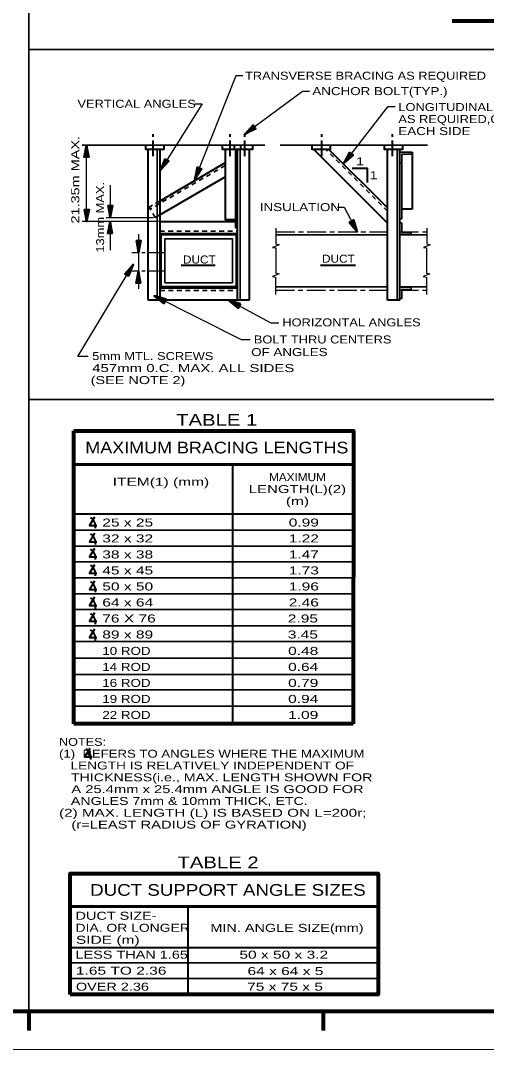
# Model space of a CAD drawing. Extents: x 55 to 190, y 198 to 264.
# Drawn here: x 102.33 to 117.13, y 198.45 to 231.1 of the extents above; entities that cross this region are included whole.
import ezdxf
from ezdxf.enums import TextEntityAlignment as Align

# ---------------------------------------------------------------- set-up
doc = ezdxf.new("R2010")
doc.units = 0
doc.header["$LTSCALE"] = 0.1
for name, pattern in [('DOT_DASHED', [7.7, 5, -1.2, 0.3, -1.2]), ('LONG_DASH_SHORT_DASH', [9.9, 6, -1.2, 1.5, -1.2]), ('SHORT_DASHED', [2.7, 1.5, -1.2])]:
    doc.linetypes.add(name, pattern=pattern)
doc.layers.add('1', color=7, linetype='Continuous', lineweight=25)
doc.layers.add('2', color=7, linetype='Continuous', lineweight=40)

msp = doc.modelspace()

# ---------------------------------------------------------------- linework, layer by layer
at = {"layer": '1', "lineweight": 80}
for p, q in [((102.5927, 199.6512), (102.5927, 199.0512)), ((111.9427, 199.6512), (111.9427, 199.0512))]:
    msp.add_line(p, q, dxfattribs=at)
at = {"layer": '1', "lineweight": 13}
msp.add_lwpolyline([(62.4915, 257.8525), (146.5927, 257.8525), (146.5927, 198.4512), (62.4915, 198.4512)], close=True, dxfattribs=at)
at = {"layer": '1', "lineweight": 80}
msp.add_lwpolyline([(65.1915, 256.6525), (145.3927, 256.6525), (145.3927, 199.6512), (65.1915, 199.6512)], close=True, dxfattribs=at)
at = {"layer": '2', "lineweight": 35}
for p, q in [((102.5927, 256.6525), (102.5927, 199.6512)), ((102.5927, 230.1829), (139.9927, 230.1829)), ((104.2928, 227.1435), (110.0877, 227.1435)), ((106.6677, 227.0075), (106.6677, 222.2344)), ((109.1561, 224.5252), (109.1561, 227.0152)), ((109.3114, 227.0075), (109.3114, 222.2344)), ((110.5738, 227.1406), (115.264, 227.1406)), ((114.2964, 227.0157), (114.2964, 222.2265)), ((114.7674, 226.9199), (114.3758, 226.9199)), ((114.4462, 226.5868), (114.3758, 226.5868)), ((114.4462, 224.8062), (114.4462, 226.8628)), ((114.4462, 226.8628), (114.7669, 226.8628)), ((114.3758, 224.8062), (114.4462, 224.8062)), ((109.1561, 224.5252), (109.2246, 224.5252)), ((110.4452, 224.2992), (113.9943, 224.2992)), ((114.3758, 224.2992), (115.2378, 224.2992)), ((110.4309, 222.6514), (113.9948, 222.6514)), ((114.3758, 222.6514), (115.2235, 222.6514)), ((102.5927, 219.0748), (139.9927, 219.0748)), ((104.0317, 214.9326), (112.9021, 214.9326)), ((104.0317, 214.4228), (112.9021, 214.4228)), ((104.0317, 213.9238), (112.9021, 213.9238)), ((104.0317, 213.4142), (112.9021, 213.4142)), ((104.0317, 212.9043), (112.9021, 212.9043)), ((104.0317, 212.4053), (112.9021, 212.4053)), ((104.0317, 211.8955), (112.9021, 211.8955)), ((104.0317, 211.3967), (112.9021, 211.3967)), ((104.0386, 210.8631), (112.9021, 210.8631)), ((104.0386, 210.3474), (112.9021, 210.3474)), ((104.0304, 209.8637), (112.9021, 209.8637)), ((104.0386, 209.3401), (112.9021, 209.3401)), ((103.9084, 201.2018), (113.6959, 201.2018)), ((103.9084, 200.6997), (113.6959, 200.6997))]:
    msp.add_line(p, q, dxfattribs=at)
at = {"layer": '2', "lineweight": 80}
for p, q in [((116.0467, 231.0941), (125.4958, 231.0941)), ((104.0267, 208.7834), (104.0288, 218.0743)), ((112.9021, 208.7834), (104.0267, 208.7834))]:
    msp.add_line(p, q, dxfattribs=at)
at = {"layer": '2'}
for p, q in [((109.4559, 227.4967), (109.7303, 227.769)), ((109.4559, 227.4967), (109.7435, 227.7521)), ((109.4559, 227.4967), (109.753, 227.738)), ((109.7639, 227.7237), (109.4559, 227.4967)), ((109.4559, 227.4967), (109.775, 227.7081)), ((109.4559, 227.4967), (109.7972, 227.6782)), ((104.4301, 227.1435), (104.374, 226.7612)), ((104.4301, 227.1435), (104.4113, 226.7612)), ((104.4307, 226.7609), (104.4301, 227.1435)), ((104.4301, 227.1435), (104.4656, 226.7607)), ((104.4301, 227.1435), (104.4484, 226.7612)), ((104.4301, 227.1435), (104.487, 226.7612)), ((106.3775, 227.0157), (106.3775, 222.2344)), ((106.7571, 227.0152), (106.7571, 222.2344)), ((109.2246, 222.2344), (109.2246, 227.0157)), ((109.608, 222.2344), (109.608, 227.0157)), ((111.6517, 227.0104), (113.9924, 224.6696)), ((113.9956, 225.1422), (112.1277, 227.0104)), ((112.6058, 226.5702), (112.7944, 226.9075)), ((112.6058, 226.5702), (112.8116, 226.8951)), ((113.9924, 222.2265), (113.9924, 227.0075)), ((114.3758, 222.2265), (114.3758, 227.0157)), ((114.7674, 226.9199), (114.7674, 225.1128)), ((108.8368, 226.581), (106.7526, 225.3721)), ((106.7725, 226.3508), (106.9294, 226.704)), ((106.7725, 226.3508), (106.9476, 226.6932)), ((106.7725, 226.3508), (106.9619, 226.6837)), ((106.977, 226.6741), (106.7725, 226.3508)), ((106.7725, 226.3508), (106.9932, 226.6638)), ((106.7725, 226.3508), (107.0246, 226.6437)), ((112.6058, 226.5702), (112.8248, 226.8842)), ((112.8391, 226.8734), (112.6058, 226.5702)), ((112.6058, 226.5702), (112.8542, 226.8615)), ((112.6058, 226.5702), (112.8836, 226.8387)), ((107.8702, 226.0685), (107.9586, 226.4447)), ((107.8702, 226.0685), (107.9787, 226.4376)), ((107.8702, 226.0685), (107.9943, 226.4307)), ((108.011, 226.4244), (107.8702, 226.0685)), ((107.8702, 226.0685), (108.0287, 226.417)), ((107.8702, 226.0685), (108.0634, 226.4032)), ((106.755, 224.9361), (108.8368, 226.1381)), ((104.4301, 224.7234), (104.3732, 225.1057)), ((104.4301, 224.7234), (104.3947, 225.1062)), ((104.4301, 224.7234), (104.4119, 225.1057)), ((104.4296, 225.106), (104.4301, 224.7234)), ((104.4301, 224.7234), (104.4862, 225.1057)), ((104.4301, 224.7234), (104.4489, 225.1057)), ((105.1786, 224.8475), (105.1218, 225.2298)), ((105.1786, 224.8475), (105.1432, 225.2303)), ((105.1786, 224.8475), (105.1604, 225.2298)), ((105.1781, 225.23), (105.1786, 224.8475)), ((105.1786, 224.8475), (105.2347, 225.2298)), ((105.1786, 224.8475), (105.1974, 225.2298)), ((114.7669, 225.1147), (114.4462, 225.1147)), ((105.1786, 224.7242), (105.1225, 224.3418)), ((105.1786, 224.7242), (105.1599, 224.3418)), ((105.1792, 224.3416), (105.1786, 224.7242)), ((105.1786, 224.7242), (105.2141, 224.3413)), ((105.1786, 224.7242), (105.1969, 224.3418)), ((105.1786, 224.7242), (105.2355, 224.3418)), ((106.7553, 224.7234), (109.1561, 224.7234)), ((113.0204, 224.3958), (112.792, 224.7078)), ((113.0204, 224.3958), (112.8108, 224.7183)), ((113.0204, 224.3958), (112.8262, 224.7257)), ((112.8418, 224.7342), (113.0204, 224.3958)), ((113.0204, 224.3958), (112.8587, 224.7429)), ((113.0204, 224.3958), (112.8918, 224.7604)), ((106.7566, 224.34), (109.2246, 224.34)), ((106.078, 223.7325), (106.0211, 224.1148)), ((106.078, 223.7325), (106.0425, 224.1154)), ((106.078, 223.7325), (106.0597, 224.1148)), ((106.0774, 224.1151), (106.078, 223.7325)), ((106.078, 223.7325), (106.134, 224.1148)), ((106.078, 223.7325), (106.0967, 224.1148)), ((105.907, 223.3523), (105.6615, 223.0538)), ((105.907, 223.3523), (105.6935, 223.0345)), ((105.7097, 223.0245), (105.907, 223.3523)), ((105.907, 223.3523), (105.725, 223.0155)), ((105.907, 223.3523), (105.7393, 223.0062)), ((105.907, 223.3523), (105.7581, 222.9956)), ((108.5105, 223.3264), (107.4371, 223.3264)), ((111.8559, 223.3377), (112.9746, 223.3377)), ((106.078, 223.1488), (106.0219, 222.7665)), ((106.078, 223.1488), (106.0592, 222.7665)), ((106.0785, 222.7662), (106.078, 223.1488)), ((106.078, 223.1488), (106.1134, 222.766)), ((106.078, 223.1488), (106.0962, 222.7665)), ((106.078, 223.1488), (106.1348, 222.7665)), ((106.922, 222.1916), (106.5801, 222.3635)), ((106.5801, 222.3635), (106.9379, 222.2225)), ((106.5801, 222.3635), (106.8963, 222.1413)), ((106.5801, 222.3635), (106.913, 222.1746)), ((106.5801, 222.3635), (106.9297, 222.2074)), ((106.5801, 222.3635), (106.9471, 222.2418)), ((106.7526, 222.6181), (109.2284, 222.6181)), ((106.3775, 222.2344), (109.608, 222.2344)), ((109.2786, 222.0447), (108.9418, 222.2262)), ((108.9418, 222.2262), (109.2956, 222.0752)), ((108.9418, 222.2262), (109.2516, 221.995)), ((108.9418, 222.2262), (109.2694, 222.0278)), ((108.9418, 222.2262), (109.2868, 222.0606)), ((108.9418, 222.2262), (109.3051, 222.0942)), ((114.3758, 222.2265), (113.9924, 222.2265)), ((109.0691, 217.0122), (109.067, 208.7834)), ((104.0338, 215.4501), (112.9021, 215.4501)), ((107.6464, 202.9825), (107.6464, 200.1975)), ((103.9084, 201.6889), (113.6959, 201.6889))]:
    msp.add_line(p, q, dxfattribs=at)
at = {"layer": '2', "linetype": 'DOT_DASHED'}
for p, q in [((106.5449, 226.7919), (106.5449, 227.4967)), ((108.9942, 226.7919), (108.9942, 227.4967)), ((109.4559, 226.7919), (109.4559, 227.4967)), ((111.8983, 226.7919), (111.8983, 227.4967)), ((114.1462, 226.7919), (114.1462, 227.4967))]:
    msp.add_line(p, q, dxfattribs=at)
at = {"layer": '2', "lineweight": 25}
for p, q in [((104.4301, 224.7234), (104.4301, 227.1435)), ((105.1786, 225.8748), (105.1786, 224.8475)), ((106.7098, 224.7234), (104.2928, 224.7234)), ((105.0477, 224.8472), (106.5523, 224.8472)), ((105.1786, 224.7242), (105.1786, 223.8151))]:
    msp.add_line(p, q, dxfattribs=at)
at = {"layer": '2', "linetype": 'SHORT_DASHED', "lineweight": 35}
for p, q in [((113.9924, 225.0475), (112.0245, 227.0157)), ((108.8368, 226.5), (106.4523, 225.1171)), ((106.7526, 225.3721), (106.4172, 225.1777)), ((106.6063, 224.8504), (106.4172, 225.1777)), ((106.6063, 224.8504), (106.7537, 224.9356)), ((106.7553, 224.4122), (109.2246, 224.4122)), ((106.7608, 222.531), (109.2246, 222.531))]:
    msp.add_line(p, q, dxfattribs=at)
at = {"layer": '2', "linetype": 'LONG_DASH_SHORT_DASH', "lineweight": 25}
for p, q in [((110.4452, 224.3982), (113.9943, 224.3982)), ((114.3756, 224.3982), (115.2378, 224.3982)), ((110.4309, 222.5384), (113.9948, 222.5384)), ((114.3758, 222.5384), (115.2235, 222.5384))]:
    msp.add_line(p, q, dxfattribs=at)
at = {"layer": '2', "linetype": 'DOT_DASHED', "lineweight": 25}
for p, q in [((106.9074, 223.7325), (105.8668, 223.7325)), ((106.9074, 223.1483), (105.8668, 223.1483))]:
    msp.add_line(p, q, dxfattribs=at)
at = {"layer": '2', "lineweight": 60}
for p, q in [((104.036, 217.0122), (112.9043, 217.0122)), ((103.9084, 202.9825), (113.6959, 202.9825))]:
    msp.add_line(p, q, dxfattribs=at)
at = {"layer": '2', "lineweight": 25}
for points in [[(109.3913, 229.3456), (109.1717, 229.3456), (107.8702, 226.0685)], [(111.508, 228.844), (111.2887, 228.844), (109.4559, 227.4967)], [(107.8702, 228.4519), (108.1055, 228.4519), (106.7725, 226.3508)], [(114.2366, 228.3579), (113.9856, 228.3579), (112.6058, 226.5702)], [(112.4023, 225.1787), (112.6084, 225.1787), (113.0204, 224.3958)], [(106.078, 224.3162), (106.078, 223.7325), (106.078, 223.1488), (106.078, 222.586)], [(110.4452, 224.5122), (110.4452, 224.0082), (110.5521, 223.9802), (110.338, 223.8957), (110.438, 223.8817), (110.438, 223.4322)], [(115.2378, 224.5122), (115.2378, 224.0082), (115.3447, 223.9802), (115.1307, 223.8957), (115.2307, 223.8817), (115.2307, 223.4322)], [(104.4791, 220.4411), (104.1494, 220.4411), (105.907, 223.3523)], [(110.438, 223.4322), (110.438, 223.0856), (110.5449, 223.0576), (110.3309, 222.9729), (110.4309, 222.9591), (110.4309, 222.408)], [(115.2307, 223.4322), (115.2307, 223.0856), (115.3376, 223.0576), (115.1235, 222.9729), (115.2235, 222.9591), (115.2235, 222.408)], [(109.6284, 220.9628), (109.3538, 220.9628), (106.5801, 222.3635)], [(110.5349, 221.4983), (110.2877, 221.4983), (108.9418, 222.2262)]]:
    msp.add_lwpolyline(points, dxfattribs=at)
at = {"layer": '2'}
for points in [[(109.7189, 227.7846), (109.8094, 227.6613), (109.4559, 227.4967)], [(109.7189, 227.7846), (109.4559, 227.4967), (109.7864, 227.693)], [(104.5063, 226.7612), (104.3534, 226.7614), (104.4301, 227.1435)], [(104.5063, 226.7612), (104.4301, 227.1435), (104.3926, 226.7609)], [(106.296, 227.1435), (106.296, 227.0157), (106.8889, 227.0157), (106.8889, 227.1435)], [(108.7383, 227.1435), (108.7383, 227.0157), (109.3313, 227.0157), (109.3313, 227.1435)], [(108.8368, 227.0157), (108.8368, 224.7832), (109.1561, 224.7832)], [(109.1148, 227.1435), (109.1148, 227.0157), (109.7078, 227.0157), (109.7078, 227.1435)], [(111.5816, 227.1435), (111.5816, 227.0157), (112.1745, 227.0157), (112.1745, 227.1435)], [(112.7791, 226.9194), (112.9, 226.8257), (112.6058, 226.5702)], [(112.7791, 226.9194), (112.6058, 226.5702), (112.8693, 226.8501)], [(113.8781, 227.1435), (113.8781, 227.0157), (114.4711, 227.0157), (114.4711, 227.1435)], [(106.913, 226.7146), (107.0421, 226.6323), (106.7725, 226.3508)], [(106.913, 226.7146), (106.7725, 226.3508), (107.0093, 226.6538)], [(107.9406, 226.4522), (108.0827, 226.3953), (107.8702, 226.0685)], [(107.9406, 226.4522), (107.8702, 226.0685), (108.0464, 226.4104)], [(112.8629, 226.4101), (113.3373, 226.4101), (113.3373, 225.9584)], [(104.3539, 225.1057), (104.4301, 224.7234), (104.4677, 225.106)], [(104.3539, 225.1057), (104.5068, 225.1054), (104.4301, 224.7234)], [(105.1024, 225.2298), (105.1786, 224.8475), (105.2162, 225.23)], [(105.1024, 225.2298), (105.2554, 225.2295), (105.1786, 224.8475)], [(105.2548, 224.3418), (105.1019, 224.3421), (105.1786, 224.7242)], [(105.2548, 224.3418), (105.1786, 224.7242), (105.1411, 224.3416)], [(112.7748, 224.6988), (112.9103, 224.7697), (113.0204, 224.3958)], [(112.7748, 224.6988), (113.0204, 224.3958), (112.8754, 224.7519)], [(106.0018, 224.1148), (106.078, 223.7325), (106.1155, 224.1151)], [(106.0018, 224.1148), (106.1547, 224.1146), (106.078, 223.7325)], [(105.7747, 222.9856), (105.6438, 223.0649), (105.907, 223.3523)], [(105.7747, 222.9856), (105.907, 223.3523), (105.6771, 223.0441)], [(106.1542, 222.7665), (106.0012, 222.7668), (106.078, 223.1488)], [(106.1542, 222.7665), (106.078, 223.1488), (106.0404, 222.7662)], [(106.9558, 222.2593), (106.8865, 222.1228), (106.5801, 222.3635)], [(106.9558, 222.2593), (106.5801, 222.3635), (106.9048, 222.1574)], [(109.3143, 222.1114), (109.2413, 221.977), (108.9418, 222.2262)], [(109.3143, 222.1114), (108.9418, 222.2262), (109.2606, 222.0111)], [(104.68, 215.3448), (104.5262, 215.0787), (104.7535, 215.0787)], [(104.68, 214.8278), (104.5262, 214.5617), (104.7535, 214.5617)], [(104.68, 214.3495), (104.5262, 214.0833), (104.7535, 214.0833)], [(104.68, 213.8328), (104.5262, 213.5666), (104.7535, 213.5666)], [(104.68, 213.3157), (104.5262, 213.0496), (104.7535, 213.0496)], [(104.68, 212.799), (104.5262, 212.5329), (104.7535, 212.5329)], [(104.68, 212.3013), (104.5262, 212.0352), (104.7535, 212.0352)], [(104.68, 211.7846), (104.5262, 211.5184), (104.7535, 211.5184)], [(104.5309, 208.0047), (104.3772, 207.7385), (104.6045, 207.7385)]]:
    msp.add_lwpolyline(points, dxfattribs=at)
at = {"layer": '2', "lineweight": 35}
for points in [[(114.3803, 224.6747), (114.443, 224.6747), (114.443, 224.3844), (114.7428, 224.3844), (114.7428, 224.317), (114.3803, 224.317)], [(106.8021, 222.6628), (109.1807, 222.6628), (109.1807, 224.2953), (106.8021, 224.2953)], [(106.9201, 222.7808), (109.0627, 222.7808), (109.0627, 224.1741), (106.9201, 224.1741)], [(114.3803, 222.2773), (114.443, 222.2773), (114.443, 222.5675), (114.7428, 222.5675), (114.7428, 222.635), (114.3803, 222.635)]]:
    msp.add_lwpolyline(points, close=True, dxfattribs=at)
at = {"layer": '2', "lineweight": 80}
msp.add_lwpolyline([(104.0288, 218.0743), (112.9043, 218.0743), (112.9021, 208.7834)], dxfattribs=at)
msp.add_lwpolyline([(103.9084, 200.1975), (103.9084, 204.0371), (113.6959, 204.0371), (113.6959, 200.1975)], close=True, dxfattribs=at)
at = {"layer": '2'}
for centre in [(104.3885, 215.0402), (104.3885, 214.5232), (104.3885, 214.0449), (104.3885, 213.5281), (104.3885, 213.0111), (104.3885, 212.4944), (104.3885, 211.9967), (104.3885, 211.48), (104.2395, 207.7001)]:
    msp.add_arc(centre, 0.3273, 351.55355, 59.07935, dxfattribs=at)

# ---------------------------------------------------------------- texts
at = {"layer": '1'}
for s, width, p in [('NOTES:', 1.2, (103.5547, 208.0847)), ('(1)  REFERS TO ANGLES WHERE THE MAXIMUM', 1.25, (103.5547, 207.7097)), ('   LENGTH IS RELATIVELY INDEPENDENT OF', 1.3, (103.5547, 207.3347)), ('   THICKNESS(i.e., MAX. LENGTH SHOWN FOR', 1.35, (103.5547, 206.9597)), ('   A 25.4mm x 25.4mm ANGLE IS GOOD FOR', 1.4, (103.5547, 206.5847)), ('   ANGLES 7mm & 10mm THICK, ETC.', 1.35, (103.5547, 206.2097)), ('(2) MAX. LENGTH (L) IS BASED ON L=200r;', 1.45, (103.5547, 205.8347)), ('   (r=LEAST RADIUS OF GYRATION)', 1.4, (103.5547, 205.4597))]:
    msp.add_text(s, height=0.25, dxfattribs=dict(at, width=width)).set_placement(p)
at = {"layer": '2'}
for s, width, p in [('TRANSVERSE BRACING AS REQUIRED', 1.2, (109.4628, 229.2208)), ('ANCHOR BOLT(TYP.)', 1.25, (111.6017, 228.7326)), ('VERTICAL ANGLES', 1.2, (104.1401, 228.3304)), ('LONGITUDINAL ANGLES', 1.2, (114.3335, 228.2262)), ('AS REQUIRED,ONE', 1.2, (114.3335, 227.8452)), ('EACH SIDE', 1.25, (114.3335, 227.4642)), ('1', 1.35, (112.9857, 226.5032)), ('1', 1.35, (113.4178, 226.0643)), ('INSULATION', 1.25, (109.9332, 225.052)), ('HORIZONTAL ANGLES', 1.2, (110.6473, 221.3941)), ('BOLT THRU CENTERS', 1.2, (109.7424, 220.8517)), (' OF ANGLES', 1.25, (109.5387, 220.4511)), ('5mm MTL. SCREWS', 1.2, (104.6079, 220.3249)), ('457mm 0.C. MAX. ALL SIDES', 1.4, (104.6079, 219.9439)), ('(SEE NOTE 2)', 1.35, (104.5598, 219.5629)), ('25 x 25', 1.45, (104.9287, 215.0437)), ('0.99', 1.45, (110.8508, 215.0437)), ('32 x 32', 1.45, (104.9287, 214.5387)), ('1.22', 1.45, (110.8508, 214.5387)), ('38 x 38', 1.45, (104.9287, 214.0307)), ('1.47', 1.45, (110.8508, 214.0307)), ('45 x 45', 1.45, (104.9287, 213.5227)), ('1.73', 1.45, (110.8508, 213.5227)), ('50 x 50', 1.45, (104.9287, 213.0147)), ('1.96', 1.45, (110.8508, 213.0147)), ('64 x 64', 1.45, (104.9287, 212.5067)), ('2.46', 1.45, (110.8508, 212.5067)), ('76 X 76', 1.45, (104.9287, 211.9987)), ('2.95', 1.45, (110.8213, 211.9987)), ('89 x 89', 1.45, (104.9287, 211.4906)), ('3.45', 1.45, (110.8213, 211.4906)), ('10 ROD', 1.25, (104.9287, 210.9697)), ('0.48', 1.45, (110.8315, 210.9697)), ('14 ROD', 1.25, (104.9287, 210.4617)), ('0.64', 1.45, (110.8315, 210.4617)), ('16 ROD', 1.25, (104.9287, 209.9537)), ('0.79', 1.45, (110.8315, 209.9537)), ('19 ROD', 1.25, (104.9287, 209.4457)), ('0.94', 1.45, (110.8315, 209.4457)), ('22 ROD', 1.25, (104.9287, 208.9377)), ('1.09', 1.45, (110.8315, 208.9377)), ('DUCT SIZE-', 1.35, (104.0785, 202.5647)), ('DIA. OR LONGER', 1.3, (104.0785, 202.1837)), ('SIDE (m)', 1.45, (104.0904, 201.8027)), ('LESS THAN 1.65', 1.35, (104.0785, 201.3307)), ('1.65 TO 2.36', 1.45, (104.0904, 200.8227)), ('OVER 2.36', 1.35, (104.0904, 200.3147))]:
    msp.add_text(s, height=0.254, dxfattribs=dict(at, width=width)).set_placement(p)
for s, rotation, width, p in [('21.35m MAX.', 90.016, 1.35, (104.1971, 226.0465)), ('13mm MAX.', 90.019, 1.2, (104.9862, 224.8552))]:
    msp.add_text(s, height=0.254, rotation=rotation, dxfattribs=dict(at, width=width)).set_placement(p, align=Align.CENTER)
for s, height, width, p in [('DUCT', 0.254, 1.1, (108.0113, 223.3891)), ('DUCT', 0.254, 1.1, (112.4282, 223.4139)), ('TABLE 1', 0.3704, 1.3, (108.5638, 218.242)), ('MAXIMUM BRACING LENGTHS', 0.3704, 1.15, (108.5677, 217.3631)), ('ITEM(1) (mm)', 0.254, 1.45, (106.7919, 216.3352)), ('MAXIMUM', 0.254, 1.1, (111.1279, 216.4834)), ('LENGTH(L)(2)', 0.254, 1.4, (111.1279, 216.1045)), ('(m)', 0.254, 1.45, (111.1279, 215.7254)), ('TABLE 2', 0.3704, 1.3, (108.6058, 204.2014)), ('DUCT SUPPORT ANGLE SIZES', 0.3704, 1.2, (108.9193, 203.3264)), ('MIN. ANGLE SIZE(mm)', 0.254, 1.35, (110.7953, 202.1813)), ('50 x 50 x 3.2', 0.254, 1.45, (110.6931, 201.3307)), ('64 x 64 x 5', 0.254, 1.45, (110.7466, 200.8108)), ('75 x 75 x 5', 0.254, 1.45, (110.7338, 200.3147))]:
    msp.add_text(s, height=height, dxfattribs=dict(at, width=width)).set_placement(p, align=Align.CENTER)

doc.saveas('drawing.dxf')
